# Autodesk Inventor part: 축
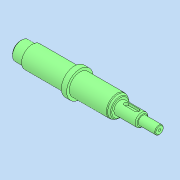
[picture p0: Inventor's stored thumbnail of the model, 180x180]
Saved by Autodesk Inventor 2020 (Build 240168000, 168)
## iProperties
Created: 2024-11
Part Number: 축
Material: 강철, 탄소
Document SubType Name: Modeling
Designer: 1강의실14
Density: 7.85 g/cm^3
Appearance: 기본값
Author: jhkim
Sending System: Autodesk Inventor 2025
Preprocessor: ST-DEVELOPER v20
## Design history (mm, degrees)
node "축1"
node "솔리드2"
node "솔리드1"
